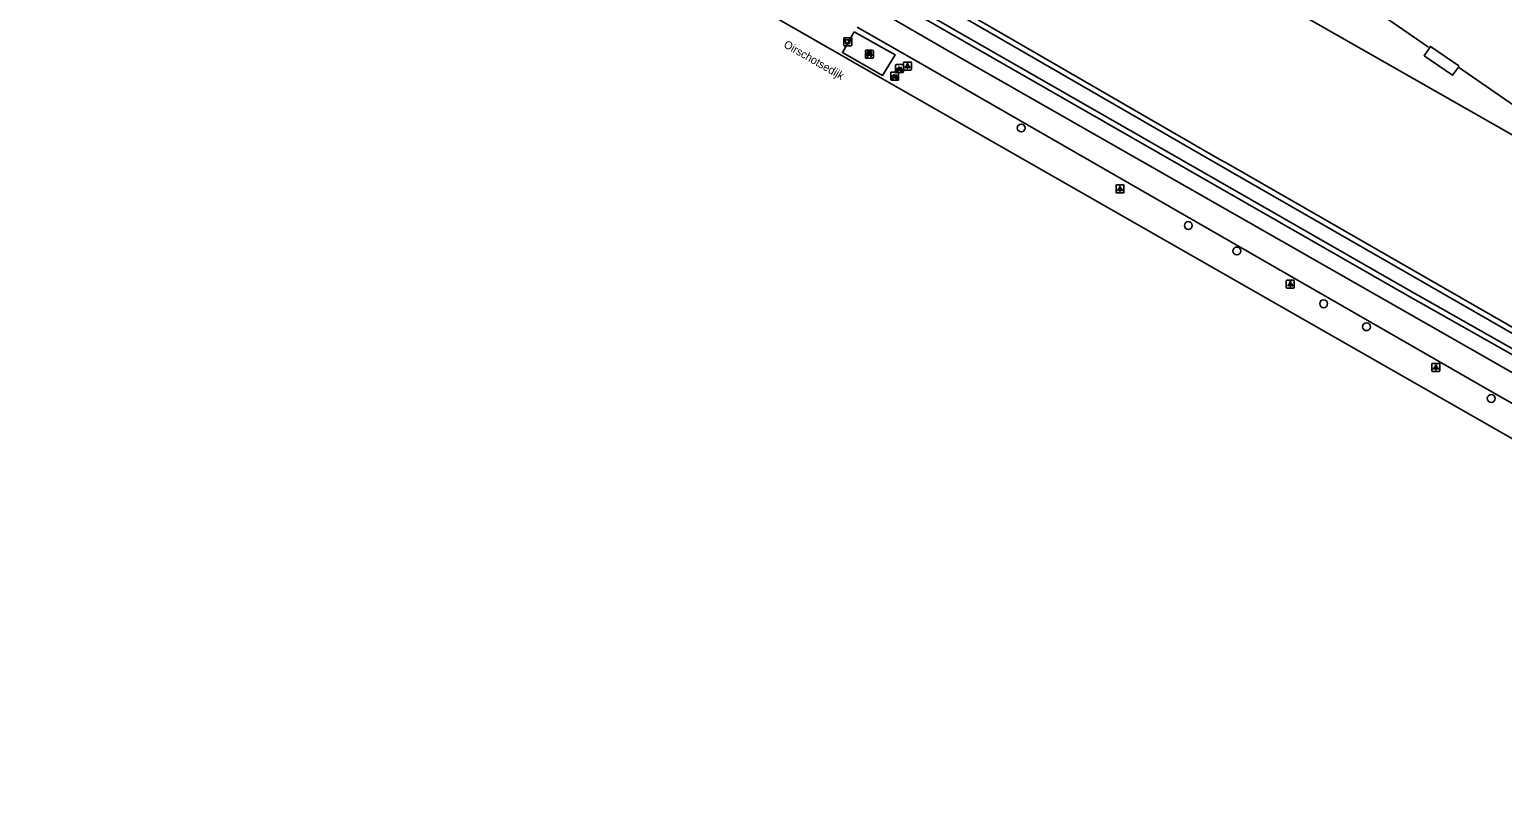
# Model space of a CAD drawing. Extents: x 157154 to 159278, y 385000 to 386650.
# Drawn here: x 158249.6 to 158433.6, y 385316.2 to 385412.2 of the extents above; entities that cross this region are included whole.
import ezdxf

# ---------------------------------------------------------------- set-up
doc = ezdxf.new("R2010")
doc.units = 0
for name, color, linetype in [('IMGEO_Afvalbak', 7, 'Continuous'), ('IMGEO_Bank', 7, 'Continuous'), ('IMGEO_Berm_groen', 7, 'Continuous'), ('IMGEO_Boom', 7, 'Continuous'), ('IMGEO_Fietsenrek', 7, 'Continuous'), ('IMGEO_Gemengd_bos', 7, 'Continuous'), ('IMGEO_Groenvoorziening', 7, 'Continuous'), ('IMGEO_Hek', 7, 'Continuous'), ('IMGEO_Lichtpunt', 7, 'Continuous'), ('IMGEO_Openbare_ruimte_label', 7, 'Continuous'), ('IMGEO_Rijbaan_lokaal_gesloten', 7, 'Continuous'), ('IMGEO_Voetpad_open', 7, 'Continuous'), ('IMGEO_Waterloop', 7, 'Continuous')]:
    doc.layers.add(name, color=color, linetype=linetype)

msp = doc.modelspace()

# ---------------------------------------------------------------- linework, layer by layer
at = {"layer": 'IMGEO_Afvalbak'}
for p, q in [((158351.33, 385410.26), (158351.33, 385411.06)), ((158351.33, 385411.06), (158351.33, 385410.26)), ((158351.43, 385411.16), (158352.22, 385411.16)), ((158352.22, 385411.16), (158351.43, 385411.16)), ((158352.32, 385411.06), (158352.32, 385410.26)), ((158352.32, 385410.26), (158352.32, 385411.06)), ((158352.22, 385410.16), (158351.43, 385410.16)), ((158351.43, 385410.16), (158352.22, 385410.16))]:
    msp.add_line(p, q, dxfattribs=at)
msp.add_lwpolyline([(158351.47, 385410.88), (158352.18, 385410.88), (158352.03, 385410.4), (158351.62, 385410.4), (158351.47, 385410.88)], dxfattribs=at)
for centre, start, end in [((158351.43, 385411.06), 90, 180), ((158351.43, 385411.06), 90, 180), ((158352.22, 385411.06), 0, 90), ((158352.22, 385411.06), 360, 90), ((158351.43, 385410.26), 180, 270), ((158351.43, 385410.26), 180, 270), ((158352.22, 385410.26), 270, 0), ((158352.22, 385410.26), 270, 0)]:
    msp.add_arc(centre, 0.1, start, end, dxfattribs=at)
at = {"layer": 'IMGEO_Bank'}
for p, q in [((158354.02, 385408.68), (158354.02, 385409.52)), ((158354.02, 385409.52), (158354.02, 385408.68)), ((158354.09, 385409.6), (158354.93, 385409.6)), ((158354.93, 385409.6), (158354.09, 385409.6)), ((158354.71, 385409), (158354.32, 385409)), ((158354.33, 385409.11), (158354.33, 385409.21)), ((158354.37, 385409.21), (158354.37, 385409.11)), ((158354.66, 385409.22), (158354.38, 385409.22)), ((158354.38, 385409.1), (158354.66, 385409.1)), ((158354.67, 385409.11), (158354.67, 385409.21)), ((158354.71, 385409.21), (158354.71, 385409.11)), ((158355.02, 385409.53), (158355.02, 385408.69)), ((158355.02, 385408.69), (158355.02, 385409.53)), ((158354.94, 385408.6), (158354.1, 385408.6)), ((158354.1, 385408.6), (158354.94, 385408.6))]:
    msp.add_line(p, q, dxfattribs=at)
for points in [[(158354.27, 385409), (158354.12, 385409), (158354.23, 385409.1), (158354.32, 385409.1)], [(158354.32, 385409.22), (158354.23, 385409.22), (158354.23, 385409.38), (158354.8, 385409.38), (158354.8, 385409.22), (158354.72, 385409.22)], [(158354.32, 385408.99), (158354.32, 385408.78), (158354.27, 385408.78), (158354.27, 385408.99)], [(158354.72, 385409.1), (158354.8, 385409.1), (158354.91, 385409), (158354.77, 385409)], [(158354.76, 385408.99), (158354.76, 385408.78), (158354.72, 385408.78), (158354.72, 385408.99)]]:
    msp.add_lwpolyline(points, dxfattribs=at)
for centre, radius, start, end in [((158354.1, 385409.52), 0.0779, 92.4484, 184.2845), ((158354.1, 385409.52), 0.0779, 92.4484, 184.2845), ((158354.27, 385408.99), 0.00671, 2.8957, 87.1043), ((158354.32, 385409.21), 0.00671, 2.8957, 87.1043), ((158354.32, 385409.11), 0.00671, 272.8957, 357.1043), ((158354.32, 385408.99), 0.00671, 92.8957, 177.1043), ((158354.38, 385409.21), 0.00671, 92.8957, 177.1043), ((158354.38, 385409.11), 0.00671, 182.8957, 267.1043), ((158354.66, 385409.21), 0.00671, 2.8957, 87.1043), ((158354.66, 385409.11), 0.00671, 272.8957, 357.1043), ((158354.72, 385409.21), 0.00671, 92.8957, 177.1043), ((158354.72, 385409.11), 0.00671, 182.8957, 267.1043), ((158354.71, 385408.99), 0.00671, 2.8957, 87.1043), ((158354.77, 385408.99), 0.00671, 92.8957, 177.1043), ((158354.94, 385409.52), 0.0779, 2.4484, 94.2845), ((158354.94, 385409.52), 0.0779, 2.4484, 94.2845), ((158354.1, 385408.68), 0.0779, 182.4484, 274.2845), ((158354.1, 385408.68), 0.0779, 182.4484, 274.2845), ((158354.94, 385408.68), 0.0779, 272.4484, 4.2845), ((158354.94, 385408.68), 0.0779, 272.4484, 4.2845)]:
    msp.add_arc(centre, radius, start, end, dxfattribs=at)
at = {"layer": 'IMGEO_Berm_groen'}
msp.add_lwpolyline([(158352.64, 385411.89), (158357.76, 385409.01), (158356.15, 385406.45), (158351.16, 385409.31), (158352.64, 385411.89)], dxfattribs=at)
at = {"layer": 'IMGEO_Boom'}
for centre in [(158373.49, 385399.88), (158394.37, 385387.7), (158400.43, 385384.53), (158411.28, 385377.93), (158416.63, 385375.06), (158432.21, 385366.1)]:
    msp.add_circle(centre, 0.489, dxfattribs=at)
at = {"layer": 'IMGEO_Fietsenrek'}
for p, q in [((158357.78, 385406.87), (158357.78, 385407.71)), ((158357.78, 385407.71), (158357.78, 385406.87)), ((158357.86, 385407.8), (158358.7, 385407.8)), ((158358.7, 385407.8), (158357.86, 385407.8)), ((158357.91, 385406.88), (158357.95, 385407.04)), ((158357.98, 385407.03), (158357.94, 385406.88)), ((158358.02, 385407.05), (158358.02, 385407.06)), ((158358.06, 385406.88), (158358.03, 385407.02)), ((158358.05, 385407.06), (158358.05, 385407.06)), ((158358.06, 385407.03), (158358.09, 385406.88)), ((158358.47, 385407.35), (158358.51, 385407.25)), ((158358.78, 385407.72), (158358.78, 385406.88)), ((158358.78, 385406.88), (158358.78, 385407.72)), ((158357.19, 385405.95), (158357.19, 385406.79)), ((158357.19, 385406.79), (158357.19, 385405.95)), ((158357.26, 385406.87), (158358.1, 385406.87)), ((158358.1, 385406.87), (158357.26, 385406.87)), ((158358.11, 385405.87), (158357.27, 385405.87)), ((158357.27, 385405.87), (158358.11, 385405.87)), ((158357.31, 385405.96), (158357.35, 385406.12)), ((158357.35, 385405.96), (158357.31, 385405.96)), ((158357.38, 385406.1), (158357.35, 385405.96)), ((158357.42, 385406.13), (158357.42, 385406.13)), ((158357.46, 385405.96), (158357.43, 385406.1)), ((158357.45, 385406.14), (158357.46, 385406.13)), ((158357.46, 385406.1), (158357.5, 385405.96)), ((158357.5, 385405.96), (158357.46, 385405.96)), ((158358.71, 385406.8), (158357.87, 385406.8)), ((158357.87, 385406.8), (158358.71, 385406.8)), ((158357.87, 385406.42), (158357.91, 385406.32)), ((158357.94, 385406.88), (158357.91, 385406.88)), ((158358.09, 385406.88), (158358.06, 385406.88)), ((158358.18, 385406.8), (158358.18, 385405.96)), ((158358.18, 385405.96), (158358.18, 385406.8))]:
    msp.add_line(p, q, dxfattribs=at)
for points in [[(158358.12, 385407.27), (158358.06, 385407.18), (158358.02, 385407.15), (158358.03, 385407.2), (158358.08, 385407.3)], [(158358.1, 385407.32), (158358.19, 385407.49), (158358.28, 385407.47), (158358.28, 385407.46), (158358.22, 385407.45), (158358.2, 385407.41), (158358.45, 385407.37)], [(158358.39, 385407.08), (158358.34, 385407.08), (158358.15, 385407.33), (158358.13, 385407.3)], [(158358.44, 385407.34), (158358.18, 385407.38), (158358.16, 385407.35), (158358.33, 385407.13), (158358.44, 385407.34)], [(158358.49, 385407.24), (158358.46, 385407.32), (158358.35, 385407.1), (158358.39, 385407.1)], [(158358.52, 385407.22), (158358.57, 385407.08), (158358.42, 385407.08)], [(158358.42, 385407.1), (158358.54, 385407.1), (158358.5, 385407.21)], [(158358.45, 385407.37), (158358.48, 385407.41), (158358.47, 385407.42), (158358.45, 385407.42), (158358.43, 385407.43), (158358.43, 385407.43), (158358.44, 385407.44), (158358.53, 385407.42), (158358.53, 385407.41), (158358.52, 385407.4), (158358.51, 385407.39), (158358.5, 385407.4), (158358.47, 385407.35)], [(158357.52, 385406.34), (158357.47, 385406.26), (158357.43, 385406.23), (158357.43, 385406.28), (158357.48, 385406.37)], [(158357.5, 385406.4), (158357.59, 385406.56), (158357.68, 385406.55), (158357.68, 385406.54), (158357.62, 385406.53), (158357.6, 385406.48), (158357.85, 385406.44)], [(158357.79, 385406.15), (158357.74, 385406.15), (158357.55, 385406.4), (158357.53, 385406.37)], [(158357.84, 385406.42), (158357.58, 385406.46), (158357.57, 385406.43), (158357.73, 385406.21), (158357.84, 385406.42)], [(158357.89, 385406.32), (158357.86, 385406.39), (158357.75, 385406.18), (158357.79, 385406.18)], [(158357.92, 385406.3), (158357.97, 385406.15), (158357.82, 385406.15)], [(158357.82, 385406.18), (158357.94, 385406.18), (158357.9, 385406.29)], [(158357.85, 385406.44), (158357.88, 385406.49), (158357.87, 385406.49), (158357.85, 385406.5), (158357.84, 385406.51), (158357.84, 385406.51), (158357.84, 385406.51), (158357.93, 385406.5), (158357.94, 385406.49), (158357.93, 385406.48), (158357.91, 385406.47), (158357.9, 385406.47), (158357.87, 385406.42)]]:
    msp.add_lwpolyline(points, dxfattribs=at)
for centre, radius, start, end in [((158357.86, 385407.72), 0.0779, 92.4484, 184.2845), ((158357.86, 385407.72), 0.0779, 92.4484, 184.2845), ((158358.02, 385407.18), 0.159, 62.6766, 242.1369), ((158358.02, 385407.18), 0.129, 63.3192, 238.903), ((158358, 385407.05), 0.0499, 12.8025, 158.6934), ((158358.02, 385407.18), 0.159, 253.9967, 271.7867), ((158358, 385407.05), 0.0174, 12.8025, 163.4502), ((158358.02, 385407.18), 0.129, 253.415, 269.0204), ((158358.02, 385407.18), 0.129, 283.6043, 43.4302), ((158358.02, 385407.18), 0.159, 283.5766, 46.6042), ((158358.55, 385407.1), 0.159, 187.0065, 105.7708), ((158358.55, 385407.1), 0.159, 113.3408, 178.3217), ((158358.55, 385407.1), 0.129, 188.6715, 104.5883), ((158358.55, 385407.1), 0.129, 113.923, 177.9556), ((158358.7, 385407.72), 0.0779, 2.4484, 94.2845), ((158358.7, 385407.72), 0.0779, 2.4484, 94.2845), ((158357.26, 385406.79), 0.0779, 92.4484, 184.2845), ((158357.26, 385406.79), 0.0779, 92.4484, 184.2845), ((158357.26, 385405.95), 0.0779, 182.4484, 274.2845), ((158357.26, 385405.95), 0.0779, 182.4484, 274.2845), ((158357.43, 385406.26), 0.159, 62.6766, 242.1369), ((158357.43, 385406.26), 0.129, 63.3192, 238.903), ((158357.4, 385406.13), 0.0499, 12.8025, 158.6934), ((158357.43, 385406.26), 0.159, 253.9967, 271.7867), ((158357.4, 385406.13), 0.0174, 12.8025, 163.4502), ((158357.43, 385406.26), 0.129, 253.415, 269.0204), ((158357.43, 385406.26), 0.159, 283.5766, 46.6042), ((158357.43, 385406.26), 0.129, 283.6043, 43.4302), ((158357.86, 385406.87), 0.0779, 182.4484, 274.2845), ((158357.86, 385406.87), 0.0779, 182.4484, 274.2845), ((158357.95, 385406.17), 0.159, 187.0065, 105.7708), ((158357.95, 385406.17), 0.159, 113.3408, 178.3217), ((158357.95, 385406.17), 0.129, 188.6715, 104.5883), ((158357.95, 385406.17), 0.129, 113.923, 177.9556), ((158358.11, 385406.79), 0.0779, 2.4484, 94.2845), ((158358.11, 385406.79), 0.0779, 2.4484, 94.2845), ((158358.11, 385405.95), 0.0779, 272.4484, 4.2845), ((158358.11, 385405.95), 0.0779, 272.4484, 4.2845), ((158358.7, 385406.87), 0.0779, 272.4484, 4.2845), ((158358.7, 385406.87), 0.0779, 272.4484, 4.2845)]:
    msp.add_arc(centre, radius, start, end, dxfattribs=at)
at = {"layer": 'IMGEO_Gemengd_bos'}
for points in [[(158500, 385337.56), (158399.37, 385395.35), (158398.01, 385396.13), (158338.67, 385430.45), (158217.1, 385500), (158197.07, 385511.61), (158180.29, 385521.19), (158127.7, 385551.21), (158080, 385578.2), (158079.87, 385578.25), (158079.74, 385578.29), (158079.61, 385578.31), (158079.48, 385578.32), (158079.34, 385578.33), (158079.21, 385578.32), (158079.07, 385578.29), (158078.94, 385578.26), (158078.82, 385578.21), (158078.69, 385578.16), (158078.58, 385578.09), (158078.46, 385578.01), (158078.36, 385577.92), (158078.27, 385577.83), (158078.19, 385577.73)], [(158361.67, 385440.85), (158380.94, 385429.76), (158474, 385376.7), (158500, 385359.29), (158529.74, 385339.1)]]:
    msp.add_lwpolyline(points, dxfattribs=at)
at = {"layer": 'IMGEO_Groenvoorziening'}
msp.add_lwpolyline([(158519.78, 385323.32), (158514.58, 385326.04), (158500, 385334.39), (158452, 385361.87), (158421.45, 385379.13), (158397.77, 385392.7), (158303.54, 385446.74), (158210.59, 385500), (158178.61, 385518.44), (158148.23, 385535.97), (158078.39, 385575.67)], dxfattribs=at)
at = {"layer": 'IMGEO_Hek'}
for points in [[(158361.67, 385440.85), (158380.94, 385429.76), (158474, 385376.7), (158500, 385359.29)], [(158424.36, 385409.98), (158416.09, 385415.67)], [(158468.69, 385384.7), (158466.23, 385381.17), (158428.1, 385407.48)]]:
    msp.add_lwpolyline(points, dxfattribs=at)
at = {"layer": 'IMGEO_Lichtpunt'}
for p, q in [((158358.78, 385408.03), (158358.78, 385407.22)), ((158358.78, 385408.03), (158358.78, 385407.22)), ((158359.68, 385408.12), (158358.88, 385408.12)), ((158359.68, 385408.12), (158358.88, 385408.12)), ((158358.88, 385407.12), (158359.68, 385407.12)), ((158358.88, 385407.12), (158359.68, 385407.12)), ((158359.78, 385407.22), (158359.78, 385408.03)), ((158359.78, 385407.22), (158359.78, 385408.03)), ((158385.34, 385392.68), (158385.34, 385391.87)), ((158385.34, 385392.68), (158385.34, 385391.87)), ((158386.24, 385392.78), (158385.43, 385392.78)), ((158386.24, 385392.78), (158385.43, 385392.78)), ((158386.33, 385391.87), (158386.33, 385392.68)), ((158386.33, 385391.87), (158386.33, 385392.68)), ((158385.43, 385391.78), (158386.24, 385391.78)), ((158385.43, 385391.78), (158386.24, 385391.78)), ((158406.61, 385380.78), (158406.61, 385379.97)), ((158406.61, 385380.78), (158406.61, 385379.97)), ((158407.51, 385380.87), (158406.71, 385380.87)), ((158407.51, 385380.87), (158406.71, 385380.87)), ((158406.71, 385379.88), (158407.51, 385379.88)), ((158406.71, 385379.88), (158407.51, 385379.88)), ((158407.61, 385379.97), (158407.61, 385380.78)), ((158407.61, 385379.97), (158407.61, 385380.78)), ((158424.8, 385370.38), (158424.8, 385369.57)), ((158424.8, 385370.38), (158424.8, 385369.57)), ((158425.7, 385370.47), (158424.89, 385370.47)), ((158425.7, 385370.47), (158424.89, 385370.47)), ((158425.79, 385369.57), (158425.79, 385370.38)), ((158425.79, 385369.57), (158425.79, 385370.38)), ((158424.89, 385369.47), (158425.7, 385369.47)), ((158424.89, 385369.47), (158425.7, 385369.47))]:
    msp.add_line(p, q, dxfattribs=at)
for points in [[(158359.16, 385407.69), (158359.19, 385407.66), (158359.01, 385407.4), (158358.97, 385407.43), (158359.16, 385407.69)], [(158359.26, 385407.64), (158359.3, 385407.64), (158359.3, 385407.32), (158359.26, 385407.32), (158359.26, 385407.64)], [(158359.37, 385407.66), (158359.41, 385407.69), (158359.59, 385407.43), (158359.55, 385407.4), (158359.37, 385407.66)], [(158385.71, 385392.34), (158385.75, 385392.32), (158385.56, 385392.05), (158385.52, 385392.08), (158385.71, 385392.34)], [(158385.81, 385392.3), (158385.86, 385392.3), (158385.86, 385391.97), (158385.81, 385391.97), (158385.81, 385392.3)], [(158385.92, 385392.32), (158385.96, 385392.34), (158386.15, 385392.08), (158386.11, 385392.05), (158385.92, 385392.32)], [(158406.99, 385380.44), (158407.02, 385380.42), (158406.84, 385380.15), (158406.8, 385380.18), (158406.99, 385380.44)], [(158407.09, 385380.4), (158407.14, 385380.4), (158407.14, 385380.07), (158407.09, 385380.07), (158407.09, 385380.4)], [(158407.2, 385380.42), (158407.24, 385380.44), (158407.42, 385380.18), (158407.38, 385380.15), (158407.2, 385380.42)], [(158425.17, 385370.04), (158425.21, 385370.01), (158425.02, 385369.75), (158424.98, 385369.78), (158425.17, 385370.04)], [(158425.27, 385369.99), (158425.32, 385369.99), (158425.32, 385369.67), (158425.27, 385369.67), (158425.27, 385369.99)], [(158425.38, 385370.01), (158425.42, 385370.04), (158425.61, 385369.78), (158425.57, 385369.75), (158425.38, 385370.01)]]:
    msp.add_lwpolyline(points, dxfattribs=at)
for centre in [(158359.28, 385407.82), (158385.84, 385392.48), (158407.11, 385380.58), (158425.3, 385370.17)]:
    msp.add_circle(centre, 0.0994, dxfattribs=at)
for centre, start, end in [((158358.88, 385408.03), 90, 180), ((158358.88, 385408.03), 90, 180), ((158358.88, 385407.22), 180, 270), ((158358.88, 385407.22), 180, 270), ((158359.68, 385408.03), 0, 90), ((158359.68, 385408.03), 0, 90), ((158359.68, 385407.22), 270, 0), ((158359.68, 385407.22), 270, 360), ((158385.43, 385392.68), 90, 180), ((158385.43, 385392.68), 90, 180), ((158386.24, 385392.68), 0, 90), ((158386.24, 385392.68), 0, 90), ((158385.43, 385391.87), 180, 270), ((158385.43, 385391.87), 180, 270), ((158386.24, 385391.87), 270, 0), ((158386.24, 385391.87), 270, 360), ((158406.71, 385380.78), 90, 180), ((158406.71, 385380.78), 90, 180), ((158406.71, 385379.97), 180, 270), ((158406.71, 385379.97), 180, 270), ((158407.51, 385380.78), 0, 90), ((158407.51, 385380.78), 0, 90), ((158407.51, 385379.97), 270, 0), ((158407.51, 385379.97), 270, 360), ((158424.89, 385370.38), 90, 180), ((158424.89, 385370.38), 90, 180), ((158425.7, 385370.38), 0, 90), ((158425.7, 385370.38), 0, 90), ((158424.89, 385369.57), 180, 270), ((158424.89, 385369.57), 180, 270), ((158425.7, 385369.57), 270, 0), ((158425.7, 385369.57), 270, 360)]:
    msp.add_arc(centre, 0.0946, start, end, dxfattribs=at)
at = {"layer": 'IMGEO_Rijbaan_lokaal_gesloten'}
msp.add_lwpolyline([(158513.29, 385316.25), (158356.14, 385406.04), (158073.11, 385568.18)], dxfattribs=at)
at = {"layer": 'IMGEO_Voetpad_open'}
for points in [[(158354.57, 385415.19), (158364.64, 385409.37), (158500.66, 385331.77), (158520.35, 385320.63)], [(158518.53, 385317.96), (158432.27, 385366.91), (158360.08, 385408.46), (158352.99, 385412.5)], [(158428.1, 385407.48), (158427.38, 385406.48), (158423.83, 385408.91), (158424.62, 385410.07), (158428.17, 385407.64), (158428.1, 385407.48)]]:
    msp.add_lwpolyline(points, dxfattribs=at)
at = {"layer": 'IMGEO_Waterloop'}
for points in [[(158210.91, 385500.57), (158303.87, 385447.31), (158398.1, 385393.27), (158421.77, 385379.69), (158452.32, 385362.44)], [(158499.67, 385336.99), (158399.05, 385394.78), (158397.69, 385395.57), (158338.34, 385429.89), (158216.77, 385499.43)]]:
    msp.add_lwpolyline(points, dxfattribs=at)

# ---------------------------------------------------------------- texts
at = {"layer": 'IMGEO_Openbare_ruimte_label'}
msp.add_text('Oirschotsedijk', height=1, rotation=330.2054, dxfattribs=at).set_placement((158343.72, 385410.04))

doc.saveas('drawing.dxf')
